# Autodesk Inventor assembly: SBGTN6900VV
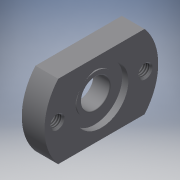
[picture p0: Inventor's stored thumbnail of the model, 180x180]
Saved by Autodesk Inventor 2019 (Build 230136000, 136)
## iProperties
Category: PARTsolutions
Company: MISUMI
Created: 2022-11
Part Number: SBGTN6900VV
Catalog Web Link: www.cadenas.de
Description: BGTNB, BGTN, SBGTN-Bearings with Housings - Space Saving, Small Flange - Non-Retained
Vendor: MISUMI
Document SubType Name: Assembly
Designer: psAdmin
Manufacturer: MISUMI
Mass: 6.2831 g
Surface Area: 42.4439 cm^2
Volume: 6.2831 cm^3
Density: 1 g/cm^3
Title: SBGTN6900VV
Author: Cadenas PARTsolutions
Comments: Bearings with Housings - Space Saving, Small Flange - Non-Retained
PSOL_IDENT_0: {$CADENAS_DATA/23d-libs/misumi/metric/12_bearing_holders/bgtnb_asmtab.prj},205 {VTYP=3D},{STYP=ASSTA
PSOL_IDENT_1: B},{NB=SBGTN6900VV},{LINA=SBGTN6900VV},{NN=BGTNB, BGTN, SBGTN},{DATE=30.06.2021 12:58:21},{GEOMDATE=
PSOL_IDENT_2: 10.07.2015 02:16:54},{VERSION=},{LINEID=90},{WBVAR=MATB,ST,SEAL,ALT1},{WBNUMERIC=}  {NB=SBGTN6900VV}
PSOL_IDENT_3: ,{LINA=SBGTN6900VV},{KT=DUMMY},{PN=SBGTN6900VV},{TYPE=SBGTN},{MATB=SS},{MATBALG= 'S' , 'Steel' , 'SS'
PSOL_IDENT_4: , 'Stainless Steel' },{ST=-},{STALG= '-' , '-' },{BN=6900},{SEAL=VV},{SEALALG= 'ZZ' , 'Double Shiel
PSOL_IDENT_5: ded' , 'VV' , 'Non-Contact Sealed Rubber Seal' , 'DD' , 'Contact Sealed Rubber Seal' },{DD=10},{D=22
PSOL_IDENT_6: },{B=6},{H=40},{W=26},{T=8},{DDHH=19},{A=31},{F=0},{M=M5},{ALT1=},{M3D=5},{PPATH=bgtnb/bgtnb_asmtpl.
PSOL_IDENT_7: prj}
NB: SBGTN6900VV
NN: BGTNB, BGTN, SBGTN
NT: Bearings with Housings - Space Saving, Small Flange - Non-Retained
NBSYN: $PN.
LINA: SBGTN6900VV
CATALOG: Misumi
PN: SBGTN6900VV
MATB: Stainless Steel
ST: -
BN: 6900
SEAL: Non-Contact Sealed Rubber Seal
DD: 10
D: 22
B: 6
H: 40
W: 26
T: 8
DDHH: 19
A: 31
F: 0
M: M5
ALT1: Bearing and Retaining Ring Assembled
SUPPLIER: MISUMI
ARTICLENO: SBGTN6900VV
BOMINFO: SBGTN6900VV
CREATOR: CADENAS GmbH
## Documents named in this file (3)
- e:\temp\worker_COMMON_2\temp\tmp_7512_18_p0Bxq\format_0\SBGTN6900VV.iam
- e:\temp\worker_COMMON_2\temp\tmp_7512_18_p0Bxq\format_0\SBGTN6900VV_h.ipt
- e:\temp\worker_COMMON_2\temp\tmp_7512_18_p0Bxq\format_0\bearing_6900.ipt
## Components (2 placed, 2 different names)
1. SBGTN6900VV_h:1 — to_bearings_XY@1 <-> to_housing_XY@2, to_bearings_Z@1 <-> to_housing_Z@2, to_bearings_YZ@1 <-> to_housing_YZ@2
2. bearing_6900:1 — to_bearings_XY@1 <-> to_housing_XY@2, to_bearings_Z@1 <-> to_housing_Z@2, to_bearings_YZ@1 <-> to_housing_YZ@2
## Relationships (3: Mate 2, Angle 1)
- to_bearings_XY@1 <-> to_housing_XY@2 [Mate]: SBGTN6900VV_h:1 ↔ bearing_6900:1
- to_bearings_Z@1 <-> to_housing_Z@2 [Mate]: SBGTN6900VV_h:1 ↔ bearing_6900:1
- to_bearings_YZ@1 <-> to_housing_YZ@2 [Angle]: SBGTN6900VV_h:1 ↔ bearing_6900:1
